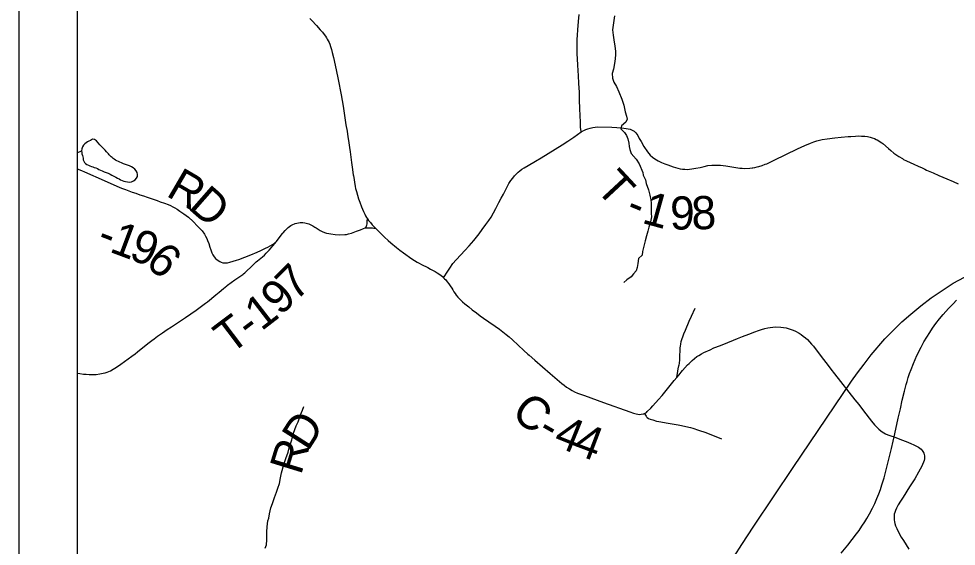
# Model space of a CAD drawing. Extents: x 0 to 34, y 0 to 22.
# Drawn here: x 2 to 3.604, y 16.93 to 17.833 of the extents above; entities that cross this region are included whole.
import ezdxf

# ---------------------------------------------------------------- set-up
doc = ezdxf.new("R2010")
doc.units = 0
for name, color, linetype in [('GM_X_Corporation', 7, 'Continuous'), ('GM_X_County_Road', 7, 'Continuous'), ('GM_X_Interchange_Ramps', 7, 'Continuous'), ('GM_X_Interstate_Route', 7, 'Continuous'), ('GM_X_Major_Lake', 7, 'Continuous'), ('GM_X_Section', 7, 'Continuous'), ('GM_X_Township_Road_Text', 7, 'Continuous'), ('SH_Cut_Line', 7, 'Continuous'), ('SH_Data', 7, 'Continuous')]:
    doc.layers.add(name, color=color, linetype=linetype)

msp = doc.modelspace()

# ---------------------------------------------------------------- linework, layer by layer
at = {"layer": 'GM_X_Corporation'}
for points in [[(2.4979, 17.8332), (2.5013, 17.8296), (2.5092, 17.8211), (2.5157, 17.8139), (2.5194, 17.8097), (2.5226, 17.8056), (2.5246, 17.803), (2.5263, 17.8004), (2.5277, 17.798), (2.5295, 17.7948), (2.5308, 17.7921), (2.5319, 17.7894), (2.5333, 17.7851), (2.5348, 17.7804), (2.5362, 17.7752), (2.5383, 17.7663), (2.5429, 17.7454), (2.5463, 17.729), (2.5514, 17.7027), (2.5547, 17.683), (2.5574, 17.6672), (2.5597, 17.6516), (2.5616, 17.6405), (2.5629, 17.6307), (2.5639, 17.6246), (2.5659, 17.6123), (2.5669, 17.6051), (2.5682, 17.5962), (2.5694, 17.5871), (2.5711, 17.5747), (2.5723, 17.5654), (2.5725, 17.5644), (2.5756, 17.546), (2.5763, 17.5426), (2.5776, 17.5372), (2.5813, 17.525), (2.5835, 17.5188), (2.5865, 17.5109), (2.5896, 17.5033), (2.5917, 17.4986), (2.5934, 17.4955), (2.595, 17.4928), (2.5964, 17.4906), (2.5985, 17.4875), (2.6014, 17.484), (2.6047, 17.4801), (2.61, 17.4746), (2.6129, 17.4715), (2.6159, 17.4686), (2.6255, 17.4593), (2.6317, 17.4536), (2.6362, 17.4497), (2.6462, 17.4415), (2.6521, 17.4369), (2.658, 17.4325), (2.6621, 17.4296), (2.6683, 17.425), (2.6721, 17.4221), (2.677, 17.419), (2.6814, 17.4164), (2.685, 17.4145), (2.6889, 17.4125), (2.6996, 17.4071), (2.7043, 17.4046), (2.7087, 17.4022), (2.7122, 17.4003), (2.7158, 17.3982), (2.7188, 17.3962), (2.7226, 17.3935), (2.7246, 17.3918), (2.7268, 17.3897), (2.7285, 17.3881), (2.7305, 17.386), (2.733, 17.383), (2.7355, 17.3796), (2.7379, 17.3762), (2.7406, 17.3719), (2.7423, 17.3693), (2.7445, 17.3658), (2.7464, 17.3629), (2.7483, 17.3601), (2.7511, 17.3568), (2.7531, 17.3544), (2.7561, 17.3513), (2.759, 17.3485), (2.763, 17.3452), (2.7696, 17.3398), (2.7757, 17.3349), (2.7828, 17.3295), (2.7894, 17.3247), (2.7948, 17.3208), (2.804, 17.3144), (2.815, 17.3067), (2.8222, 17.3017), (2.8251, 17.2997), (2.8278, 17.2975), (2.8309, 17.2952), (2.834, 17.2926), (2.8386, 17.2885), (2.8446, 17.2833), (2.8543, 17.2744), (2.8641, 17.2652), (2.8707, 17.2592), (2.8729, 17.2571), (2.8825, 17.2489), (2.9092, 17.226), (2.929, 17.2089), (2.9328, 17.2058), (2.9372, 17.2027), (2.9421, 17.1996), (2.9464, 17.197), (2.9507, 17.1948), (2.9558, 17.1925), (2.9608, 17.1905), (2.9675, 17.1882), (2.9787, 17.1842), (3.0005, 17.1766), (3.045, 17.1603), (3.0517, 17.158), (3.0559, 17.1568), (3.059, 17.1562), (3.0614, 17.1561), (3.0649, 17.1562), (3.0678, 17.1567), (3.0694, 17.1571), (3.0704, 17.1575)], [(3.0704, 17.1575), (3.0717, 17.1582), (3.0735, 17.1594), (3.0752, 17.1607), (3.0813, 17.1668), (3.0848, 17.1705), (3.0944, 17.1814), (3.1004, 17.1886), (3.121, 17.2137), (3.1257, 17.2193), (3.1289, 17.2232), (3.1356, 17.2311), (3.1441, 17.2408), (3.1465, 17.2432), (3.1519, 17.2481), (3.1558, 17.2516), (3.16, 17.2548), (3.1634, 17.257), (3.1681, 17.2597), (3.1717, 17.2616), (3.1825, 17.2667), (3.1892, 17.2696), (3.2004, 17.2741), (3.2131, 17.2791), (3.2226, 17.283), (3.2293, 17.2857), (3.2379, 17.2891), (3.2488, 17.2935), (3.259, 17.2973), (3.2656, 17.2997), (3.2706, 17.3014), (3.2762, 17.303), (3.2815, 17.3042), (3.2856, 17.3049), (3.2899, 17.3054), (3.2938, 17.3056), (3.3033, 17.3053), (3.308, 17.3047), (3.3125, 17.3039), (3.3163, 17.303), (3.3213, 17.3014), (3.3247, 17.3), (3.3286, 17.2981), (3.3352, 17.2947), (3.3382, 17.2929), (3.3419, 17.2901), (3.3456, 17.287), (3.3489, 17.2839), (3.3526, 17.2801), (3.3563, 17.2759), (3.3592, 17.2725), (3.3691, 17.2598), (3.3767, 17.2499), (3.3845, 17.2398), (3.3893, 17.2333), (3.3954, 17.2252), (3.4304, 17.1811), (3.4368, 17.1728), (3.4449, 17.1622), (3.4586, 17.1447), (3.464, 17.1384), (3.4685, 17.1336), (3.4712, 17.1309), (3.4745, 17.128), (3.4769, 17.1263), (3.4797, 17.1245), (3.4826, 17.123), (3.4867, 17.1213), (3.4917, 17.1195), (3.4973, 17.1174)], [(3.0704, 17.1575), (3.0718, 17.1547), (3.073, 17.1528), (3.0738, 17.1518), (3.0752, 17.1506), (3.0774, 17.1492), (3.08, 17.148), (3.0844, 17.1465), (3.091, 17.1446), (3.095, 17.1438), (3.111, 17.1408), (3.1144, 17.1403), (3.128, 17.1383), (3.1306, 17.1378), (3.1492, 17.1336), (3.1528, 17.1326), (3.1626, 17.1293), (3.1752, 17.1248), (3.2022, 17.1144)], [(3.4973, 17.1174), (3.5097, 17.1127), (3.518, 17.1096), (3.5258, 17.1063), (3.5313, 17.1039), (3.5357, 17.1019), (3.5388, 17.1), (3.5413, 17.0983), (3.5434, 17.0963), (3.5451, 17.0944), (3.5465, 17.0924), (3.5479, 17.0896), (3.5486, 17.0872), (3.5491, 17.0849), (3.5492, 17.0835), (3.5491, 17.08), (3.5486, 17.0772), (3.5477, 17.0741), (3.5461, 17.0703), (3.5441, 17.0663), (3.542, 17.0621), (3.5392, 17.0571), (3.5325, 17.0458), (3.5239, 17.032), (3.5129, 17.0147), (3.5084, 17.0076), (3.5043, 17.0013), (3.5014, 16.9957), (3.4995, 16.9916), (3.4984, 16.9884), (3.4977, 16.9853), (3.4973, 16.9821), (3.4975, 16.9754), (3.498, 16.9721), (3.4986, 16.9693), (3.4999, 16.9653), (3.5019, 16.9606), (3.5044, 16.9555), (3.5096, 16.9462), (3.5132, 16.9403), (3.5227, 16.9257)]]:
    msp.add_lwpolyline(points, dxfattribs=at)
at = {"layer": 'GM_X_County_Road'}
msp.add_lwpolyline([(3.2238, 16.9128), (3.2367, 16.9333), (3.2572, 16.9646), (3.3248, 17.0653), (3.4246, 17.2127), (3.4345, 17.2271), (3.4459, 17.2421), (3.4579, 17.2577), (3.4816, 17.2853), (3.4994, 17.3031), (3.5108, 17.3142), (3.5261, 17.3277), (3.5428, 17.3416), (3.5606, 17.3552), (3.5797, 17.3682), (3.5985, 17.3802), (3.6175, 17.391)], dxfattribs=at)
at = {"layer": 'GM_X_Interchange_Ramps'}
for points in [[(2.1, 17.9098), (2.1, 14.1), (6.5113, 14.1), (6.5389, 15.3228), (6.5411, 15.4243), (6.5572, 16.1864), (6.5647, 16.5359), (6.5883, 17.471), (6.5943, 17.9356)], [(3.4069, 16.9186), (3.4179, 16.9322), (3.4328, 16.9516), (3.4373, 16.9576), (3.4423, 16.9649), (3.4472, 16.9722), (3.4507, 16.9779), (3.4555, 16.9861), (3.4604, 16.9957), (3.4643, 17.0037), (3.468, 17.0123), (3.4711, 17.0199), (3.4738, 17.0276), (3.4765, 17.0355), (3.4788, 17.0426), (3.4803, 17.0474), (3.4817, 17.0522), (3.485, 17.0656), (3.4878, 17.0773), (3.4926, 17.0975), (3.4957, 17.1104), (3.4973, 17.1174), (3.5002, 17.1309), (3.5042, 17.1497), (3.508, 17.1656), (3.5113, 17.1801), (3.515, 17.196), (3.5162, 17.2005), (3.518, 17.207), (3.5195, 17.2123), (3.5215, 17.2189), (3.5237, 17.2257), (3.5264, 17.2329), (3.5304, 17.2431), (3.5362, 17.2565), (3.5434, 17.271), (3.5484, 17.2801), (3.5535, 17.2883), (3.5582, 17.2959), (3.563, 17.3036), (3.5687, 17.3116), (3.5749, 17.3193), (3.581, 17.3267), (3.5904, 17.3373), (3.5981, 17.3454), (3.6043, 17.3516)]]:
    msp.add_lwpolyline(points, dxfattribs=at)
at = {"layer": 'GM_X_Interstate_Route'}
for points in [[(2.9619, 17.6393), (2.9614, 17.6437), (2.9611, 17.6469), (2.9609, 17.6519), (2.9607, 17.6561), (2.9598, 17.6788), (2.9594, 17.694), (2.9589, 17.7074), (2.9582, 17.7223), (2.9575, 17.7356), (2.957, 17.7435), (2.9563, 17.7542), (2.9557, 17.7637), (2.9551, 17.7736), (2.955, 17.7822), (2.9551, 17.7926), (2.9554, 17.7973), (2.9559, 17.8046), (2.9566, 17.8138), (2.9576, 17.828), (2.9584, 17.8402)], [(2.7268, 17.3897), (2.7287, 17.3928), (2.7318, 17.3975), (2.7374, 17.4064), (2.7426, 17.4141), (2.7481, 17.4206), (2.7562, 17.429), (2.7633, 17.4363), (2.7703, 17.4442), (2.7782, 17.4535), (2.7874, 17.4649), (2.7929, 17.4721), (2.7989, 17.4809), (2.804, 17.4875), (2.808, 17.4934), (2.816, 17.5084), (2.8212, 17.5184), (2.825, 17.5256), (2.8289, 17.533), (2.8347, 17.5444), (2.8385, 17.5507), (2.8419, 17.556), (2.845, 17.5602), (2.8481, 17.5642), (2.8512, 17.5675), (2.8545, 17.5706), (2.8573, 17.5729), (2.8608, 17.5753), (2.8646, 17.5776), (2.8716, 17.582), (2.8839, 17.5892), (2.8935, 17.5948), (2.9297, 17.6169), (2.9394, 17.6234), (2.9494, 17.63), (2.9619, 17.6393), (2.9635, 17.6403), (2.9664, 17.6418), (2.9698, 17.6433), (2.9737, 17.6447), (2.9777, 17.6459), (2.9817, 17.6467), (2.986, 17.6474), (2.9902, 17.6477), (3.0146, 17.6475), (3.0229, 17.6468), (3.03, 17.6462), (3.0352, 17.6458), (3.0392, 17.6452), (3.0424, 17.6446), (3.0456, 17.6438), (3.0481, 17.6428), (3.0504, 17.6417), (3.0524, 17.6405), (3.0544, 17.6389), (3.0557, 17.6376), (3.059, 17.6328), (3.0614, 17.6282), (3.0644, 17.6228), (3.069, 17.6145), (3.0755, 17.6053), (3.0803, 17.5996), (3.0838, 17.5959), (3.0878, 17.5931), (3.0939, 17.5896), (3.0993, 17.5868), (3.1054, 17.5844), (3.1102, 17.5827), (3.1148, 17.5809), (3.1196, 17.5793), (3.1272, 17.5773), (3.1315, 17.5763), (3.1356, 17.5756), (3.1391, 17.5752), (3.1431, 17.5751), (3.1475, 17.5753), (3.1516, 17.5758), (3.158, 17.577), (3.1657, 17.5786), (3.1727, 17.5802), (3.1786, 17.5815), (3.1854, 17.5824), (3.2006, 17.5822), (3.2094, 17.5813), (3.2231, 17.5791), (3.2337, 17.5774), (3.2372, 17.5771), (3.2408, 17.5769), (3.2507, 17.5772), (3.2546, 17.5777), (3.2556, 17.5779), (3.259, 17.5785), (3.2629, 17.5794), (3.2661, 17.5802), (3.2716, 17.5817), (3.277, 17.5838), (3.2796, 17.5848), (3.2921, 17.5909), (3.3322, 17.6101), (3.3445, 17.6158), (3.3545, 17.6201), (3.3601, 17.6223), (3.3651, 17.624), (3.3695, 17.6252), (3.3741, 17.6262), (3.383, 17.6274), (3.3958, 17.6288), (3.4067, 17.63), (3.4186, 17.6311), (3.4231, 17.6316), (3.4311, 17.6322), (3.4359, 17.6324), (3.4416, 17.6322), (3.4471, 17.6317), (3.4518, 17.6311), (3.4561, 17.6303), (3.4598, 17.6292), (3.4635, 17.6278), (3.4665, 17.6264), (3.4683, 17.6255), (3.4762, 17.6205), (3.4778, 17.6194), (3.4875, 17.6109), (3.4917, 17.6072), (3.4967, 17.6031), (3.5001, 17.6006), (3.5054, 17.5972), (3.5114, 17.5935), (3.5136, 17.5921), (3.5184, 17.5898), (3.5247, 17.5868), (3.5313, 17.5838), (3.5385, 17.5805), (3.5451, 17.5776), (3.5496, 17.5755), (3.553, 17.574), (3.564, 17.5691), (3.574, 17.5647), (3.5806, 17.5619), (3.5877, 17.559), (3.5982, 17.5545), (3.6071, 17.5505)], [(2.1, 17.5762), (2.1072, 17.5734), (2.1125, 17.5712), (2.1461, 17.5561), (2.1676, 17.5466), (2.1755, 17.5432), (2.1825, 17.5405), (2.1938, 17.5364), (2.2, 17.5343), (2.2072, 17.5318), (2.2133, 17.5297), (2.2195, 17.5276), (2.2246, 17.5259), (2.2314, 17.5235), (2.2367, 17.5217), (2.2421, 17.5198), (2.2491, 17.5173), (2.2553, 17.5149), (2.2595, 17.5132), (2.2634, 17.5113), (2.2672, 17.5092), (2.2708, 17.5069), (2.2758, 17.5039), (2.2826, 17.4991), (2.2905, 17.4933), (2.2985, 17.4861), (2.306, 17.4782), (2.3137, 17.4698), (2.3179, 17.4641), (2.3197, 17.461), (2.3217, 17.457), (2.3231, 17.4536), (2.3252, 17.4484), (2.3271, 17.4419), (2.3284, 17.4376), (2.3303, 17.4324), (2.3319, 17.4292), (2.3341, 17.4257), (2.3365, 17.4228), (2.3395, 17.4203), (2.3437, 17.4175), (2.3462, 17.4164), (2.3491, 17.4155), (2.3514, 17.4151), (2.354, 17.415), (2.3571, 17.4153), (2.3609, 17.4162), (2.3725, 17.4198), (2.3765, 17.4211), (2.387, 17.4251), (2.3969, 17.429), (2.4079, 17.4336), (2.4141, 17.4364), (2.422, 17.4402), (2.4259, 17.4422), (2.4342, 17.4468), (2.4368, 17.4486), (2.4389, 17.45), (2.4396, 17.4508), (2.4401, 17.4514), (2.4513, 17.4653), (2.4524, 17.4667), (2.4557, 17.4704), (2.4587, 17.4734), (2.461, 17.4756), (2.4633, 17.4774), (2.4655, 17.4789), (2.4676, 17.4801), (2.4731, 17.4824), (2.4759, 17.4833), (2.4785, 17.4839), (2.4812, 17.4842), (2.4837, 17.4843), (2.4858, 17.4842), (2.4892, 17.4838), (2.4918, 17.4832), (2.4961, 17.4817), (2.4999, 17.4801), (2.5031, 17.4785), (2.5065, 17.4765), (2.5086, 17.4752), (2.5158, 17.4706), (2.5188, 17.469), (2.523, 17.4673), (2.5262, 17.4662), (2.5302, 17.4652), (2.534, 17.4646), (2.5412, 17.4638), (2.5481, 17.4634), (2.558, 17.4636), (2.5608, 17.464), (2.5638, 17.4646), (2.569, 17.4662), (2.5775, 17.4692), (2.5848, 17.4719), (2.5898, 17.4738), (2.5924, 17.4751), (2.5931, 17.4756), (2.5944, 17.477), (2.5951, 17.4785), (2.5955, 17.4798), (2.5958, 17.4819), (2.5962, 17.4866), (2.5964, 17.4906)], [(2.5924, 17.4751), (2.5939, 17.4752), (2.5969, 17.4754), (2.6029, 17.4753), (2.6051, 17.4751), (2.6076, 17.4748), (2.61, 17.4746)], [(2.1202, 17.2243), (2.1263, 17.2242), (2.1323, 17.2245), (2.1385, 17.2252), (2.1446, 17.2263), (2.1478, 17.2271), (2.1513, 17.2282), (2.154, 17.2292), (2.1569, 17.2305), (2.1614, 17.2331), (2.1673, 17.2369), (2.1749, 17.242), (2.1933, 17.2554), (2.1993, 17.2598), (2.2034, 17.2632), (2.2179, 17.2748), (2.223, 17.2788), (2.2278, 17.2825), (2.2316, 17.2855), (2.2376, 17.2898), (2.2458, 17.2954), (2.2541, 17.3011), (2.2612, 17.306), (2.2851, 17.3215), (2.3035, 17.3343), (2.3195, 17.346), (2.3227, 17.3485), (2.3371, 17.3603), (2.343, 17.3653), (2.3501, 17.3712), (2.3557, 17.3759), (2.3572, 17.3771), (2.3631, 17.3815), (2.3698, 17.386), (2.3764, 17.3907), (2.3831, 17.3954), (2.3845, 17.3966), (2.3869, 17.3984), (2.3888, 17.4002), (2.3908, 17.402), (2.3964, 17.4074), (2.4016, 17.4124), (2.4063, 17.4169), (2.4082, 17.4186), (2.4167, 17.4255), (2.4202, 17.4286), (2.4234, 17.4317), (2.426, 17.4344), (2.4284, 17.4371), (2.4378, 17.4486), (2.4389, 17.45)], [(3.1257, 17.2193), (3.1273, 17.2301), (3.128, 17.234), (3.1292, 17.2392), (3.1296, 17.2408), (3.1301, 17.2429), (3.1304, 17.2448), (3.1306, 17.2482), (3.1308, 17.2519), (3.131, 17.2586), (3.1312, 17.2631), (3.1314, 17.2678), (3.1316, 17.27), (3.1319, 17.2728), (3.1324, 17.2763), (3.1333, 17.2806), (3.1379, 17.2937), (3.1403, 17.2999), (3.1469, 17.3154), (3.1506, 17.3239), (3.1568, 17.338)], [(2.1, 17.2267), (2.1012, 17.2265), (2.1045, 17.2258), (2.1105, 17.225), (2.1154, 17.2246), (2.1202, 17.2243)]]:
    msp.add_lwpolyline(points, dxfattribs=at)
at = {"layer": 'GM_X_Township_Road_Text'}
msp.add_line((2.1, 17.6032), (2.1076, 17.6068), dxfattribs=at)
for points in [[(3.0191, 17.8379), (3.0159, 17.8141), (3.0165, 17.8046), (3.0177, 17.7966), (3.0198, 17.7856), (3.0206, 17.7772), (3.0207, 17.7703), (3.0197, 17.7597), (3.0173, 17.7467), (3.0151, 17.739), (3.0156, 17.731), (3.018, 17.7242), (3.0222, 17.717), (3.0265, 17.708), (3.0316, 17.6951), (3.0352, 17.6849), (3.0372, 17.6738), (3.0396, 17.6659), (3.0408, 17.661), (3.0383, 17.6556), (3.0308, 17.6498), (3.0297, 17.6444), (3.0359, 17.6384), (3.0397, 17.6328), (3.0421, 17.6271), (3.0437, 17.6199), (3.0441, 17.6145), (3.045, 17.6092), (3.0477, 17.6024), (3.0562, 17.5926), (3.0612, 17.5847), (3.0675, 17.57), (3.0683, 17.565), (3.0722, 17.5575), (3.0731, 17.551), (3.077, 17.5404), (3.0794, 17.5309), (3.081, 17.5233), (3.0815, 17.5176), (3.0818, 17.4997), (3.0822, 17.494), (3.0804, 17.4852), (3.0779, 17.4764), (3.0761, 17.4695), (3.074, 17.4615), (3.0714, 17.4527), (3.0672, 17.4344), (3.0661, 17.4286), (3.0601, 17.4228), (3.0591, 17.4141), (3.0577, 17.4072), (3.0563, 17.4018), (3.0514, 17.3964), (3.0473, 17.3914), (3.0402, 17.3864), (3.035, 17.3817)], [(2.4747, 17.1363), (2.478, 17.1435), (2.482, 17.1554), (2.4853, 17.1635), (2.4875, 17.1696)], [(2.4213, 16.9272), (2.4235, 16.9329), (2.4241, 16.9413), (2.4241, 16.947), (2.4243, 16.9554), (2.4249, 16.9638), (2.4259, 16.9737), (2.4278, 16.9787), (2.4288, 16.9859), (2.4313, 16.9959), (2.4338, 17.0035), (2.4375, 17.0139), (2.4408, 17.0227), (2.4429, 17.0296), (2.4458, 17.038), (2.4476, 17.0475), (2.4497, 17.0563), (2.4537, 17.0705), (2.457, 17.0804), (2.4606, 17.0915), (2.4628, 17.0988), (2.4671, 17.1125), (2.47, 17.124), (2.4747, 17.1363)]]:
    msp.add_lwpolyline(points, dxfattribs=at)
for points in [[(2.1227, 17.6246), (2.113, 17.619), (2.1076, 17.6068), (2.1096, 17.5966)], [(2.1096, 17.5966), (2.1122, 17.5871), (2.1218, 17.581), (2.1317, 17.5776), (2.1427, 17.5726), (2.1561, 17.5669), (2.1691, 17.5601), (2.1797, 17.5552), (2.1927, 17.554), (2.203, 17.5632), (2.1988, 17.5753), (2.1858, 17.5822), (2.1728, 17.5875), (2.1633, 17.5924), (2.1503, 17.6049), (2.1389, 17.6171), (2.1263, 17.6266), (2.1227, 17.6246)]]:
    msp.add_spline(points, degree=3, dxfattribs=at)
at = {"layer": 'SH_Cut_Line'}
msp.add_lwpolyline([(2.1, 17.9098), (2.1, 14.1), (8.9, 14.1), (8.9, 17.8921), (8.5492, 17.9006), (8.3297, 17.9059), (7.6027, 17.9156), (6.5943, 17.9356), (6.24, 17.9427), (6.0729, 17.9463), (5.6339, 17.9555), (5.3871, 17.9608), (4.994, 17.969), (4.9368, 17.9702), (4.9267, 17.9702), (4.5919, 17.9719), (4.4481, 17.9728), (4.1825, 17.9744), (3.7128, 17.9822), (3.7063, 17.8588), (3.604, 17.8577), (2.9484, 17.8857), (2.6711, 17.8975), (2.4376, 17.9025)], close=True, dxfattribs=at)
at = {"layer": 'SH_Data'}
for p, q in [((2, 21), (2, 14)), ((2.1, 20.9), (2.1, 14.1))]:
    msp.add_line(p, q, dxfattribs=at)

# ---------------------------------------------------------------- texts
at = {"layer": 'GM_X_Major_Lake'}
for s, rotation, p in [('C', 320.8111, (2.84, 17.1544)), ('4', 338.0023, (2.9124, 17.1038)), ('-', 330.1136, (2.8845, 17.1192)), ('4', 339.2912, (2.9461, 17.0902))]:
    msp.add_text(s, height=0.0568, rotation=rotation, dxfattribs=at).set_placement(p)
at = {"layer": 'GM_X_Section'}
for s, rotation, p in [('R', 329.7207, (2.2502, 17.5309)), ('T', 312.9085, (2.9848, 17.5416)), ('D', 318.6756, (2.2881, 17.509)), ('1', 344.5113, (3.0641, 17.484)), ('9', 359.3184, (3.1136, 17.4724)), ('8', 2.1213, (3.1516, 17.472)), ('-', 337.4934, (3.0354, 17.4954)), ('1', 339.3824, (2.1533, 17.4348)), ('-', 338.5705, (2.1308, 17.4437)), ('9', 339.7078, (2.1864, 17.4224)), ('6', 318.3652, (2.2145, 17.4131)), ('7', 44.6587, (2.4735, 17.3481)), ('9', 43.8963, (2.4476, 17.3233)), ('1', 37.676, (2.4149, 17.2975)), ('T', 37.0593, (2.3618, 17.2574)), ('-', 37.173, (2.3958, 17.283)), ('D', 57.4042, (2.4947, 17.0916)), ('R', 72.9, (2.4826, 17.0507))]:
    msp.add_text(s, height=0.0568, rotation=rotation, dxfattribs=at).set_placement(p)

doc.saveas('drawing.dxf')
